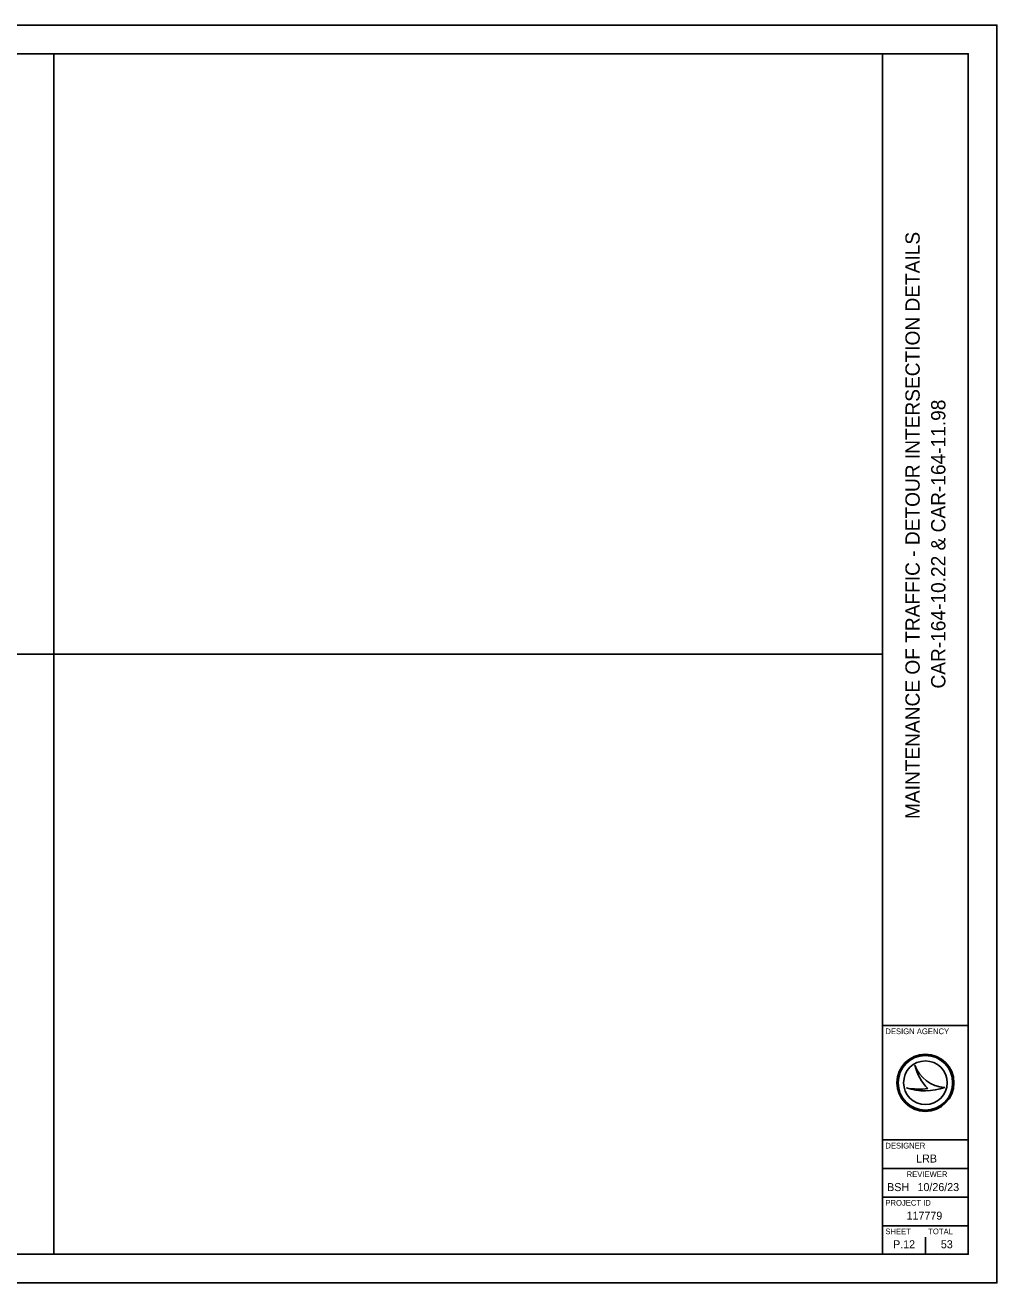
# Model space of a CAD drawing. Extents: x 0 to 1214, y 0 to 883.
# Drawn here: x 340 to 680, y 0 to 440 of the extents above; entities that cross this region are included whole.
import ezdxf

# ---------------------------------------------------------------- set-up
doc = ezdxf.new("R2010")
doc.units = 0
for name, color, linetype in [('GM_X_Section', 7, 'Continuous'), ('SH_Border', 7, 'Continuous'), ('SH_Cut_Line', 7, 'Continuous'), ('SH_Data', 7, 'Continuous')]:
    doc.layers.add(name, color=color, linetype=linetype)

msp = doc.modelspace()

# ---------------------------------------------------------------- linework, layer by layer
at = {"layer": 'GM_X_Section'}
for p, q in [((350, 430), (350, 10)), ((30, 220), (640, 220))]:
    msp.add_line(p, q, dxfattribs=at)
at = {"layer": 'SH_Border'}
for p, q in [((640, 10), (640, 430)), ((640, 90), (670, 90)), ((640, 50), (670, 50)), ((640, 40), (670, 40)), ((640, 30), (670, 30)), ((640, 20), (670, 20))]:
    msp.add_line(p, q, dxfattribs=at)
msp.add_lwpolyline([(30, 430), (670, 430), (670, 10), (30, 10)], close=True, dxfattribs=at)
at = {"layer": 'SH_Cut_Line'}
msp.add_lwpolyline([(0, 0), (680, 0), (680, 440), (0, 440)], close=True, dxfattribs=at)
at = {"layer": 'SH_Data'}
for p, q in [((651.35, 76.19), (651.35, 76.19)), ((648.34, 68.19), (648.34, 68.19)), ((655, 70), (655, 70)), ((661.75, 68.37), (661.75, 68.37)), ((647.5, 13.5), (647.5, 13.5)), ((655, 10), (655, 16))]:
    msp.add_line(p, q, dxfattribs=at)
for radius in [10, 9.54, 9.54, 7.64]:
    msp.add_circle((655, 70), radius, dxfattribs=at)
for centre, radius, start, end in [((662.32, 79.95), 11.6, 198.9257, 198.9319), ((666.93, 79.4), 15.91, 191.6379, 191.6421), ((662.32, 79.95), 11.6, 198.9319, 267.1657), ((666.93, 79.4), 15.91, 191.6421, 226.0947), ((654.79, 87.4), 20.26, 251.4576, 290.0832), ((652.96, 93.09), 25.32, 259.4964, 259.4995), ((654.79, 87.4), 20.26, 251.4527, 251.4576), ((652.96, 93.09), 25.32, 259.4995, 276.6672)]:
    msp.add_arc(centre, radius, start, end, dxfattribs=at)

# ---------------------------------------------------------------- texts
for s, p in [('MAINTENANCE OF TRAFFIC - DETOUR INTERSECTION DETAILS', (653, 162.26)), ('CAR-164-10.22 & CAR-164-11.98', (662, 207.91))]:
    msp.add_text(s, height=5, rotation=90, dxfattribs=at).set_placement(p)
for s, height, p in [('DESIGN AGENCY', 2, (641, 87)), ('DESIGNER', 2, (641, 47)), ('LRB', 2.8, (651.77, 42.1)), ('REVIEWER', 2, (648.44, 37)), ('BSH', 2.8, (641.6, 32.1)), ('10/26/23', 2.8, (652.23, 32.1)), ('PROJECT ID', 2, (641, 27)), ('117779', 2.8, (648.41, 22.1)), ('SHEET', 2, (641, 17)), ('TOTAL', 2, (656, 17)), ('P.12', 2.8, (643.69, 12.1)), ('53', 2.8, (660.4, 12.1))]:
    msp.add_text(s, height=height, dxfattribs=at).set_placement(p)

doc.saveas('drawing.dxf')
